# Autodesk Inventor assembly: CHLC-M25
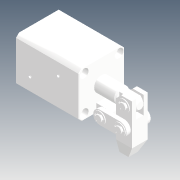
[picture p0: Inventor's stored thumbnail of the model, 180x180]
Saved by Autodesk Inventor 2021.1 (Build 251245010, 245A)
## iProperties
Company: Microsoft
Created: 2019-11
Part Number: CHLC-M25
Description: STEP AP214
Document SubType Name: Assembly
Designer: user
Title: CHLC-M25.STEP
Author: Windows
Revision Number: ÈÎºÎ
Sending System: SolidWorks 2015
Preprocessor: SwSTEP 2.0
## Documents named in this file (10)
- D:\Vault_2016\Projekty\Clamptek\Hydraulic\CHLC\CHLC-25\Inventor\CHLC-M25\CHLC-M25.iam
- D:\Vault_2016\Projekty\Clamptek\Hydraulic\CHLC\CHLC-25\Inventor\CHLC-M25\CHLC-25ZC.ipt
- D:\Vault_2016\Projekty\Clamptek\Hydraulic\CHLC\CHLC-25\Inventor\CHLC-M25\CHLC-25LG.ipt
- D:\Vault_2016\Projekty\Clamptek\Hydraulic\CHLC\CHLC-25\Inventor\CHLC-M25\CHLC-25HSG.ipt
- D:\Vault_2016\Projekty\Clamptek\Hydraulic\CHLC\CHLC-25\Inventor\CHLC-M25\CHLC-25DX.ipt
- D:\Vault_2016\Projekty\Clamptek\Hydraulic\CHLC\CHLC-25\Inventor\CHLC-M25\CHLC-25CX.ipt
- D:\Vault_2016\Projekty\Clamptek\Hydraulic\CHLC\CHLC-25\Inventor\CHLC-M25\CHLC-25KKDC.ipt
- D:\Vault_2016\Projekty\Clamptek\Hydraulic\CHLC\CHLC-25\Inventor\CHLC-M25\chlc-m25bt.ipt
- D:\Vault_2016\Projekty\Clamptek\Hydraulic\CHLC\CHLC-25\Inventor\CHLC-M25\socket set screw cup point_iso_ISO 4029 - M5 x 6-N.ipt
- D:\Vault_2016\Projekty\Clamptek\Hydraulic\CHLC\CHLC-25\Inventor\CHLC-M25\Ñ¹±Û.ipt
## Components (17 placed, 17 different names)
1. CHLC-25ZC_1
2. CHLC-25LG_2
3. CHLC-25LG_3
4. CHLC-25HSG_4
5. CHLC-25DX_5
6. CHLC-25CX_6
7. CHLC-25CX_7
8. CHLC-25KKDC_8
9. CHLC-25KKDC_9
10. CHLC-25KKDC_10
11. CHLC-25KKDC_11
12. CHLC-25KKDC_12
13. CHLC-25KKDC_13
14. chlc-m25bt_14
15. socket set screw cup point_iso_ISO 4029 - M5 x 6-N_15
16. socket set screw cup point_iso_ISO 4029 - M5 x 6-N_16
17. Ñ¹±Û_17
